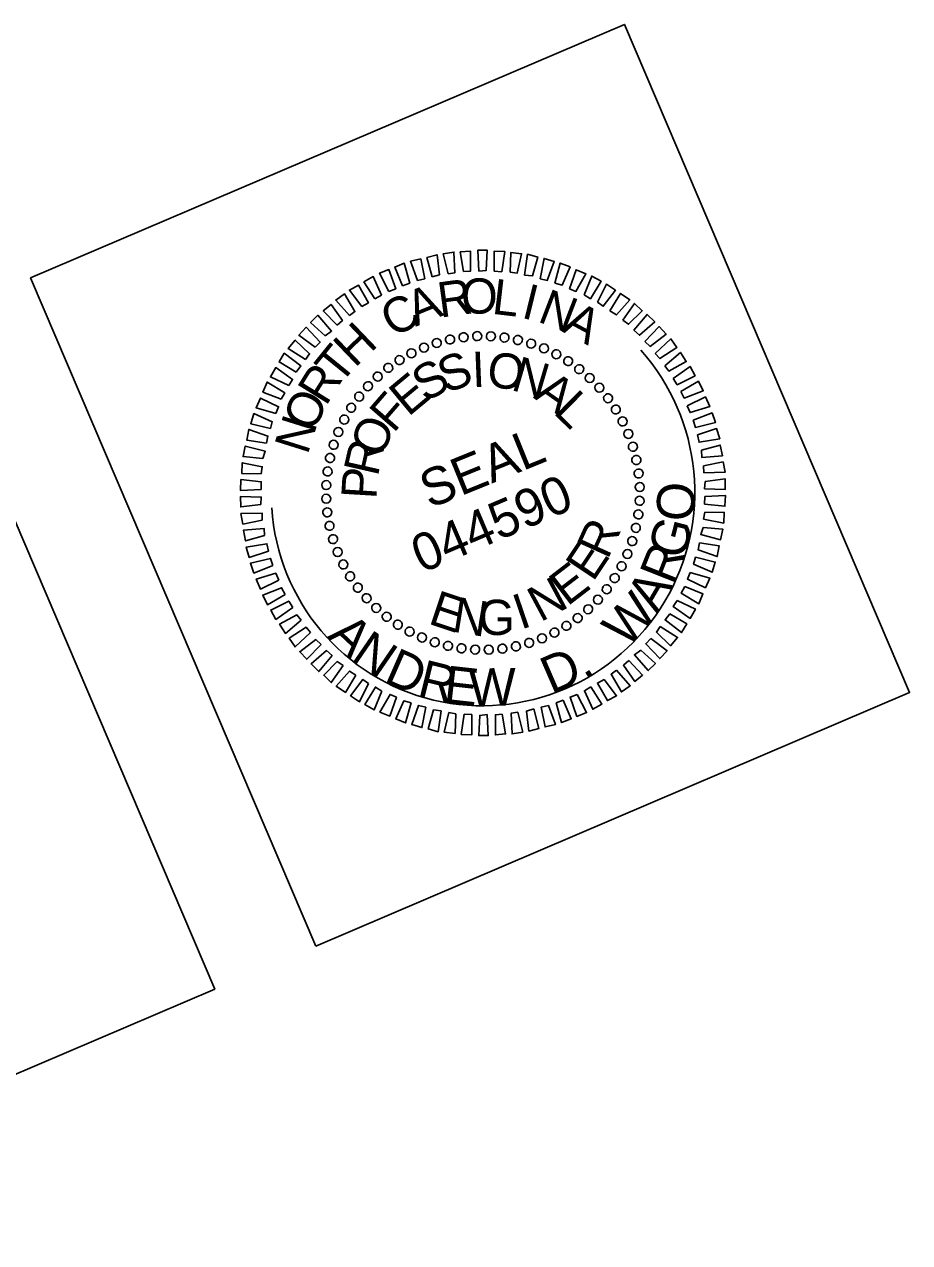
# Model space of a CAD drawing. Extents: x 1882804 to 2194450, y 87424 to 845437.
# Drawn here: x 2194312.8 to 2194449.9, y 87477.3 to 87666 of the extents above; entities that cross this region are included whole.
import ezdxf

# ---------------------------------------------------------------- set-up
doc = ezdxf.new("R2010")
doc.units = 0
for name, color, linetype in [('Scratch_Level_1', 7, 'Continuous'), ('Sheet PE Seal Cell', 7, 'Continuous'), ('Sheet Plot Border Inside CELL', 7, 'Continuous')]:
    doc.layers.add(name, color=color, linetype=linetype)

msp = doc.modelspace()

# ---------------------------------------------------------------- linework, layer by layer
at = {"layer": 'Scratch_Level_1'}
for points in [[(2194357.93, 87523.27), (2194449.9, 87562.54), (2194405.72, 87666.01), (2194313.75, 87626.74)], [(2194250.33, 87477.33), (2194342.29, 87516.6), (2194298.12, 87620.06), (2194206.15, 87580.8)]]:
    msp.add_lwpolyline(points, close=True, dxfattribs=at)
at = {"layer": 'Sheet PE Seal Cell'}
for p, q in [((2194374.67, 87615.97), (2194374.67, 87615.97)), ((2194376.69, 87616.67), (2194376.69, 87616.67)), ((2194378.74, 87617.18), (2194378.74, 87617.18)), ((2194380.78, 87617.58), (2194380.78, 87617.58)), ((2194382.92, 87617.75), (2194382.92, 87617.75)), ((2194385.04, 87617.71), (2194385.04, 87617.71)), ((2194387.16, 87617.56), (2194387.16, 87617.56)), ((2194389.24, 87617.13), (2194389.24, 87617.13)), ((2194391.31, 87616.6), (2194391.31, 87616.6)), ((2194372.73, 87615.09), (2194372.73, 87615.09)), ((2194393.26, 87615.85), (2194393.26, 87615.85)), ((2194395.22, 87614.95), (2194395.22, 87614.95)), ((2194369.12, 87612.81), (2194369.12, 87612.81)), ((2194370.93, 87614), (2194370.93, 87614)), ((2194397, 87613.87), (2194397, 87613.87)), ((2194398.75, 87612.61), (2194398.75, 87612.61)), ((2194367.48, 87611.48), (2194367.48, 87611.48)), ((2194400.38, 87611.25), (2194400.38, 87611.25)), ((2194364.64, 87608.37), (2194364.64, 87608.37)), ((2194366, 87610), (2194366, 87610)), ((2194401.86, 87609.78), (2194401.86, 87609.78)), ((2194363.39, 87606.62), (2194363.39, 87606.62)), ((2194403.19, 87608.13), (2194403.19, 87608.13)), ((2194362.3, 87604.84), (2194362.3, 87604.84)), ((2194404.38, 87606.33), (2194404.38, 87606.33)), ((2194361.4, 87602.88), (2194361.4, 87602.88)), ((2194405.47, 87604.53), (2194405.47, 87604.53)), ((2194360.66, 87600.93), (2194360.66, 87600.93)), ((2194406.35, 87602.58), (2194406.35, 87602.58)), ((2194407.05, 87600.57), (2194407.05, 87600.57)), ((2194360.12, 87598.86), (2194360.12, 87598.86)), ((2194407.56, 87598.52), (2194407.56, 87598.52)), ((2194359.69, 87596.78), (2194359.69, 87596.78)), ((2194407.96, 87596.48), (2194407.96, 87596.48)), ((2194359.54, 87594.66), (2194359.54, 87594.66)), ((2194408.13, 87594.34), (2194408.13, 87594.34)), ((2194359.5, 87592.54), (2194359.5, 87592.54)), ((2194408.09, 87592.21), (2194408.09, 87592.21)), ((2194359.68, 87590.4), (2194359.68, 87590.4)), ((2194407.94, 87590.1), (2194407.94, 87590.1)), ((2194360.07, 87588.36), (2194360.07, 87588.36)), ((2194407.51, 87588.02), (2194407.51, 87588.02)), ((2194360.58, 87586.31), (2194360.58, 87586.31)), ((2194406.98, 87585.95), (2194406.98, 87585.95)), ((2194361.28, 87584.29), (2194361.28, 87584.29)), ((2194406.23, 87583.99), (2194406.23, 87583.99)), ((2194362.16, 87582.35), (2194362.16, 87582.35)), ((2194405.33, 87582.03), (2194405.33, 87582.03)), ((2194363.25, 87580.55), (2194363.25, 87580.55)), ((2194404.25, 87580.25), (2194404.25, 87580.25)), ((2194364.44, 87578.74), (2194364.44, 87578.74)), ((2194402.99, 87578.5), (2194402.99, 87578.5)), ((2194365.78, 87577.1), (2194365.78, 87577.1)), ((2194401.63, 87576.87), (2194401.63, 87576.87)), ((2194367.25, 87575.62), (2194367.25, 87575.62)), ((2194400.16, 87575.4), (2194400.16, 87575.4)), ((2194368.88, 87574.26), (2194368.88, 87574.26)), ((2194370.63, 87573.01), (2194370.63, 87573.01)), ((2194396.71, 87572.87), (2194396.71, 87572.87)), ((2194398.51, 87574.06), (2194398.51, 87574.06)), ((2194372.41, 87571.92), (2194372.41, 87571.92)), ((2194374.37, 87571.02), (2194374.37, 87571.02)), ((2194392.96, 87570.9), (2194392.96, 87570.9)), ((2194394.91, 87571.78), (2194394.91, 87571.78)), ((2194376.32, 87570.28), (2194376.32, 87570.28)), ((2194378.4, 87569.74), (2194378.4, 87569.74)), ((2194380.48, 87569.31), (2194380.48, 87569.31)), ((2194382.59, 87569.16), (2194382.59, 87569.16)), ((2194384.72, 87569.12), (2194384.72, 87569.12)), ((2194386.86, 87569.3), (2194386.86, 87569.3)), ((2194388.9, 87569.69), (2194388.9, 87569.69)), ((2194390.95, 87570.2), (2194390.95, 87570.2))]:
    msp.add_line(p, q, dxfattribs=at)
for points in [[(2194383.17, 87627.76), (2194383, 87631.01), (2194384.47, 87631.01), (2194384.33, 87627.89)], [(2194373.67, 87626.34), (2194372.61, 87629.31), (2194374.19, 87629.67), (2194374.81, 87626.62)], [(2194375.96, 87626.9), (2194375.14, 87629.92), (2194376.71, 87630.32), (2194377.08, 87627.22)], [(2194378.44, 87627.38), (2194377.65, 87630.46), (2194379.31, 87630.75), (2194379.47, 87627.55)], [(2194380.82, 87627.71), (2194380.31, 87630.76), (2194381.88, 87630.9), (2194381.89, 87627.8)], [(2194385.54, 87627.77), (2194385.53, 87630.88), (2194387.18, 87630.84), (2194386.73, 87627.7)], [(2194388.02, 87627.62), (2194388.14, 87630.68), (2194389.8, 87630.49), (2194389.1, 87627.45)], [(2194390.27, 87627.16), (2194390.73, 87630.41), (2194392.29, 87629.97), (2194391.48, 87627.05)], [(2194392.67, 87626.61), (2194393.27, 87629.76), (2194394.85, 87629.27), (2194393.78, 87626.34)], [(2194369.22, 87624.65), (2194367.77, 87627.45), (2194369.25, 87628.04), (2194370.31, 87625.07)], [(2194371.38, 87625.52), (2194370.15, 87628.42), (2194371.63, 87629), (2194372.47, 87625.93)], [(2194394.95, 87625.95), (2194395.79, 87629.04), (2194397.32, 87628.43), (2194396.09, 87625.64)], [(2194397.22, 87625.07), (2194398.24, 87627.99), (2194399.77, 87627.37), (2194398.2, 87624.65)], [(2194365.07, 87622.3), (2194363.14, 87624.85), (2194364.55, 87625.61), (2194366.08, 87622.89)], [(2194367.09, 87623.48), (2194365.39, 87626.12), (2194366.82, 87626.95), (2194368.1, 87624.07)], [(2194399.47, 87624.14), (2194400.66, 87627.02), (2194402.11, 87626.21), (2194400.47, 87623.51)], [(2194401.54, 87622.97), (2194402.93, 87625.77), (2194404.33, 87624.84), (2194402.44, 87622.35)], [(2194363.14, 87620.9), (2194361.01, 87623.3), (2194362.39, 87624.26), (2194363.98, 87621.52)], [(2194403.48, 87621.64), (2194405.12, 87624.34), (2194406.54, 87623.36), (2194404.49, 87621.01)], [(2194361.25, 87619.4), (2194359.08, 87621.64), (2194360.29, 87622.63), (2194362.05, 87620.12)], [(2194405.48, 87620.17), (2194407.31, 87622.8), (2194408.48, 87621.66), (2194406.37, 87619.55)], [(2194359.37, 87617.76), (2194357.11, 87619.85), (2194358.22, 87620.95), (2194360.37, 87618.5)], [(2194407.19, 87618.64), (2194409.24, 87621.09), (2194410.43, 87619.92), (2194408.05, 87617.85)], [(2194357.81, 87615.99), (2194355.32, 87617.87), (2194356.43, 87619.09), (2194358.62, 87616.81)], [(2194408.88, 87616.88), (2194411.11, 87619.2), (2194412.19, 87618.03), (2194409.73, 87616.14)], [(2194356.35, 87614.1), (2194353.67, 87615.8), (2194354.75, 87617.1), (2194356.97, 87615)], [(2194410.51, 87615.05), (2194412.92, 87617.29), (2194413.82, 87615.94), (2194411.22, 87614.25)], [(2194354.87, 87612.15), (2194352.25, 87613.72), (2194353.04, 87615.06), (2194355.62, 87613.1)], [(2194411.96, 87613.14), (2194414.4, 87615.19), (2194415.31, 87613.79), (2194412.62, 87612.32)], [(2194353.74, 87610.09), (2194350.91, 87611.41), (2194351.72, 87612.86), (2194354.34, 87611.03)], [(2194413.27, 87611.17), (2194415.9, 87613.03), (2194416.68, 87611.58), (2194413.9, 87610.18)], [(2194352.55, 87607.95), (2194349.75, 87609.07), (2194350.37, 87610.6), (2194353.13, 87608.93)], [(2194414.45, 87609.15), (2194417.19, 87610.74), (2194417.93, 87609.27), (2194415, 87608.12)], [(2194351.75, 87605.76), (2194348.69, 87606.62), (2194349.37, 87608.12), (2194352.16, 87606.78)], [(2194415.45, 87606.94), (2194418.28, 87608.31), (2194418.93, 87606.8), (2194415.9, 87605.87)], [(2194350.91, 87603.4), (2194347.85, 87604.15), (2194348.34, 87605.73), (2194351.19, 87604.47)], [(2194416.35, 87604.69), (2194419.29, 87605.84), (2194419.82, 87604.33), (2194416.72, 87603.59)], [(2194350.3, 87601.14), (2194347.24, 87601.63), (2194347.54, 87603.28), (2194350.51, 87602.23)], [(2194417.04, 87602.46), (2194420.01, 87603.41), (2194420.48, 87601.82), (2194417.28, 87601.3)], [(2194417.66, 87600.04), (2194420.57, 87600.86), (2194420.9, 87599.21), (2194417.7, 87598.95)], [(2194349.72, 87598.79), (2194346.66, 87599.06), (2194347.01, 87600.69), (2194350.09, 87599.89)], [(2194349.47, 87596.42), (2194346.46, 87596.45), (2194346.53, 87598.11), (2194349.64, 87597.49)], [(2194417.99, 87597.65), (2194421, 87598.25), (2194421.31, 87596.65), (2194418.03, 87596.56)], [(2194349.45, 87593.99), (2194346.25, 87593.83), (2194346.33, 87595.5), (2194349.48, 87595.16)], [(2194418.23, 87595.23), (2194421.34, 87595.61), (2194421.35, 87593.98), (2194418.14, 87594.08)], [(2194349.4, 87591.65), (2194346.3, 87591.27), (2194346.28, 87592.9), (2194349.49, 87592.79)], [(2194418.18, 87592.89), (2194421.38, 87593.04), (2194421.3, 87591.38), (2194418.15, 87591.72)], [(2194349.64, 87589.22), (2194346.64, 87588.62), (2194346.32, 87590.23), (2194349.6, 87590.31)], [(2194418.16, 87590.46), (2194421.18, 87590.43), (2194421.1, 87588.76), (2194417.99, 87589.38)], [(2194349.98, 87586.84), (2194347.06, 87586.01), (2194346.73, 87587.66), (2194349.94, 87587.92)], [(2194417.91, 87588.09), (2194420.98, 87587.82), (2194420.62, 87586.19), (2194417.54, 87586.98)], [(2194417.34, 87585.73), (2194420.39, 87585.25), (2194420.09, 87583.59), (2194417.12, 87584.64)], [(2194350.59, 87584.41), (2194347.63, 87583.46), (2194347.16, 87585.05), (2194350.36, 87585.58)], [(2194351.28, 87582.18), (2194348.35, 87581.03), (2194347.81, 87582.54), (2194350.91, 87583.29)], [(2194416.72, 87583.47), (2194419.78, 87582.72), (2194419.3, 87581.15), (2194416.44, 87582.4)], [(2194352.19, 87579.93), (2194349.35, 87578.56), (2194348.7, 87580.08), (2194351.73, 87581)], [(2194415.89, 87581.11), (2194418.94, 87580.26), (2194418.26, 87578.76), (2194415.48, 87580.09)], [(2194353.18, 87577.72), (2194350.44, 87576.13), (2194349.7, 87577.61), (2194352.64, 87578.76)], [(2194415.08, 87578.93), (2194417.88, 87577.8), (2194417.27, 87576.28), (2194414.5, 87577.94)], [(2194354.36, 87575.7), (2194351.74, 87573.84), (2194350.95, 87575.3), (2194353.73, 87576.69)], [(2194413.89, 87576.78), (2194416.72, 87575.46), (2194415.92, 87574.01), (2194413.29, 87575.84)], [(2194355.68, 87573.73), (2194353.23, 87571.69), (2194352.32, 87573.09), (2194355.01, 87574.55)], [(2194412.77, 87574.72), (2194415.39, 87573.16), (2194414.59, 87571.82), (2194412.02, 87573.77)], [(2194357.13, 87571.82), (2194354.71, 87569.58), (2194353.82, 87570.94), (2194356.41, 87572.63)], [(2194411.28, 87572.77), (2194413.96, 87571.07), (2194412.88, 87569.77), (2194410.67, 87571.88)], [(2194358.75, 87569.99), (2194356.53, 87567.67), (2194355.45, 87568.84), (2194357.91, 87570.73)], [(2194409.82, 87570.89), (2194412.32, 87569), (2194411.2, 87567.79), (2194409.02, 87570.07)], [(2194360.45, 87568.24), (2194358.39, 87565.78), (2194357.2, 87566.96), (2194359.58, 87569.03)], [(2194408.26, 87569.11), (2194410.53, 87567.03), (2194409.42, 87565.92), (2194407.26, 87568.37)], [(2194362.16, 87566.7), (2194360.33, 87564.08), (2194359.16, 87565.21), (2194361.26, 87567.32)], [(2194406.39, 87567.47), (2194408.55, 87565.23), (2194407.34, 87564.24), (2194405.58, 87566.76)], [(2194364.15, 87565.24), (2194362.51, 87562.54), (2194361.1, 87563.51), (2194363.15, 87565.86)], [(2194404.49, 87565.98), (2194406.63, 87563.57), (2194405.25, 87562.61), (2194403.65, 87565.36)], [(2194366.09, 87563.91), (2194364.71, 87561.1), (2194363.31, 87562.03), (2194365.19, 87564.52)], [(2194368.17, 87562.74), (2194366.97, 87559.86), (2194365.53, 87560.66), (2194367.16, 87563.36)], [(2194400.54, 87563.39), (2194402.25, 87560.75), (2194400.81, 87559.93), (2194399.53, 87562.8)], [(2194402.57, 87564.57), (2194404.5, 87562.03), (2194403.08, 87561.27), (2194401.55, 87563.98)], [(2194370.41, 87561.8), (2194369.39, 87558.89), (2194367.86, 87559.5), (2194369.44, 87562.23)], [(2194372.68, 87560.93), (2194371.84, 87557.83), (2194370.32, 87558.44), (2194371.55, 87561.23)], [(2194396.25, 87561.35), (2194397.49, 87558.46), (2194396, 87557.87), (2194395.16, 87560.94)], [(2194398.41, 87562.22), (2194399.87, 87559.42), (2194398.38, 87558.84), (2194397.32, 87561.81)], [(2194374.96, 87560.27), (2194374.36, 87557.11), (2194372.78, 87557.6), (2194373.85, 87560.53)], [(2194377.36, 87559.71), (2194376.9, 87556.46), (2194375.35, 87556.9), (2194376.15, 87559.83)], [(2194379.61, 87559.25), (2194379.49, 87556.2), (2194377.83, 87556.38), (2194378.54, 87559.42)], [(2194389.2, 87559.5), (2194389.99, 87556.41), (2194388.32, 87556.12), (2194388.17, 87559.32)], [(2194391.68, 87559.98), (2194392.49, 87556.96), (2194390.93, 87556.55), (2194390.55, 87559.66)], [(2194393.97, 87560.53), (2194395.03, 87557.56), (2194393.44, 87557.2), (2194392.82, 87560.26)], [(2194382.1, 87559.1), (2194382.11, 87556), (2194380.46, 87556.03), (2194380.91, 87559.17)], [(2194384.46, 87559.11), (2194384.64, 87555.87), (2194383.16, 87555.87), (2194383.31, 87558.98)], [(2194386.81, 87559.16), (2194387.32, 87556.12), (2194385.75, 87555.97), (2194385.74, 87559.08)]]:
    msp.add_lwpolyline(points, close=True, dxfattribs=at)
for centre, major_axis in [((2194378.72, 87617.19), (-0.146, 0.682)), ((2194380.81, 87617.55), (-0.086, 0.692)), ((2194382.92, 87617.72), (-0.026, 0.697)), ((2194385.04, 87617.7), (0.035, 0.697)), ((2194387.15, 87617.5), (0.096, 0.691)), ((2194389.23, 87617.12), (0.155, 0.68)), ((2194374.67, 87615.95), (-0.263, 0.646)), ((2194376.66, 87616.66), (-0.205, 0.667)), ((2194391.28, 87616.56), (0.214, 0.664)), ((2194393.26, 87615.82), (0.271, 0.643)), ((2194370.9, 87614.01), (-0.371, 0.591)), ((2194372.74, 87615.06), (-0.318, 0.621)), ((2194395.18, 87614.91), (0.326, 0.617)), ((2194397.01, 87613.84), (0.379, 0.586)), ((2194367.52, 87611.46), (-0.468, 0.517)), ((2194369.15, 87612.81), (-0.421, 0.556)), ((2194398.73, 87612.61), (0.428, 0.551)), ((2194366.01, 87609.97), (-0.511, 0.475)), ((2194400.35, 87611.24), (0.475, 0.511)), ((2194401.84, 87609.73), (0.517, 0.468)), ((2194364.64, 87608.36), (-0.551, 0.428)), ((2194403.19, 87608.1), (0.556, 0.421)), ((2194363.41, 87606.63), (-0.586, 0.379)), ((2194404.39, 87606.36), (0.591, 0.371)), ((2194362.34, 87604.8), (-0.617, 0.326)), ((2194405.44, 87604.51), (0.621, 0.318)), ((2194361.43, 87602.88), (-0.643, 0.271)), ((2194406.32, 87602.59), (0.646, 0.263)), ((2194360.69, 87600.9), (-0.664, 0.214)), ((2194407.04, 87600.59), (0.667, 0.205)), ((2194360.13, 87598.85), (-0.68, 0.155)), ((2194407.57, 87598.54), (0.682, 0.146)), ((2194359.75, 87596.77), (-0.691, 0.096)), ((2194407.93, 87596.45), (0.692, 0.086)), ((2194359.55, 87594.66), (-0.697, 0.035)), ((2194408.1, 87594.34), (0.697, 0.026)), ((2194359.54, 87592.54), (-0.697, -0.026)), ((2194408.08, 87592.22), (0.697, -0.035)), ((2194359.71, 87590.43), (-0.692, -0.086)), ((2194407.88, 87590.11), (0.691, -0.096)), ((2194360.06, 87588.34), (-0.682, -0.146)), ((2194407.5, 87588.02), (0.68, -0.155)), ((2194360.6, 87586.28), (-0.667, -0.205)), ((2194406.94, 87585.98), (0.664, -0.214)), ((2194361.31, 87584.29), (-0.646, -0.263)), ((2194406.2, 87583.99), (0.643, -0.271)), ((2194362.19, 87582.36), (-0.621, -0.318)), ((2194405.29, 87582.08), (0.617, -0.326)), ((2194363.24, 87580.52), (-0.591, -0.371)), ((2194404.22, 87580.25), (0.586, -0.379)), ((2194364.44, 87578.77), (-0.556, -0.421)), ((2194402.99, 87578.52), (0.551, -0.428)), ((2194365.8, 87577.14), (-0.517, -0.468)), ((2194367.28, 87575.63), (-0.475, -0.511)), ((2194401.62, 87576.9), (0.511, -0.475)), ((2194368.9, 87574.26), (-0.428, -0.551)), ((2194398.48, 87574.06), (0.421, -0.556)), ((2194400.11, 87575.42), (0.468, -0.517)), ((2194370.63, 87573.03), (-0.379, -0.586)), ((2194372.46, 87571.96), (-0.326, -0.617)), ((2194394.89, 87571.81), (0.318, -0.621)), ((2194396.74, 87572.86), (0.371, -0.591)), ((2194374.37, 87571.05), (-0.271, -0.643)), ((2194376.36, 87570.31), (-0.214, -0.664)), ((2194390.97, 87570.22), (0.205, -0.667)), ((2194392.97, 87570.93), (0.263, -0.646)), ((2194378.4, 87569.75), (-0.155, -0.68)), ((2194380.49, 87569.37), (-0.096, -0.691)), ((2194382.6, 87569.17), (-0.035, -0.697)), ((2194384.72, 87569.16), (0.026, -0.697)), ((2194386.83, 87569.33), (0.086, -0.692)), ((2194388.92, 87569.68), (0.146, -0.682))]:
    msp.add_ellipse(centre, major_axis=major_axis, ratio=0.999708, dxfattribs=at)
at = {"layer": 'Sheet Plot Border Inside CELL'}
msp.add_ellipse((2194383.82, 87593.44), major_axis=(10.38, 31.31), ratio=0.993455, start_param=1.958957, end_param=5.764947, dxfattribs=at)

# ---------------------------------------------------------------- texts
at = {"layer": 'Sheet PE Seal Cell'}
for s, height, rotation, p in [('R', 5.46, 7.7417, (2194377.18, 87620.57)), ('O', 5.46, 0.5417, (2194380.45, 87621.18)), ('L', 5.46, 353.3414, (2194385.08, 87621.2)), ('I', 5.46, 346.1407, (2194389.6, 87620.61)), ('C', 5.46, 29.3404, (2194369.96, 87617.38)), ('A', 5.46, 22.1409, (2194373.36, 87619.15)), ('N', 5.46, 338.9395, (2194392.1, 87620.04)), ('A', 5.46, 331.7377, (2194395.85, 87618.54)), ('H', 5.46, 43.74, (2194363.95, 87612.71)), ('T', 5.46, 50.9403, (2194361.68, 87610)), ('S', 5.46, 21.021, (2194378.1, 87608.8)), ('I', 5.46, 2.3102, (2194382.2, 87609.81)), ('O', 5.46, 352.9541, (2194384.25, 87609.95)), ('N', 5.46, 343.5972, (2194387.99, 87609.44)), ('R', 5.46, 58.1411, (2194359.49, 87606.75)), ('E', 5.46, 39.7316, (2194372.24, 87605.14)), ('S', 5.46, 30.3762, (2194374.91, 87607.38)), ('A', 5.46, 324.8808, (2194391.52, 87608.21)), ('O', 5.46, 65.3423, (2194357.59, 87602.68)), ('F', 5.46, 49.0876, (2194369.96, 87602.58)), ('L', 5.46, 315.5214, (2194394.57, 87605.88)), ('N', 5.46, 72.5441, (2194356.65, 87599.22)), ('O', 5.46, 67.8018, (2194368.14, 87598.7)), ('SEAL', 5.811, 22.1206, (2194375.55, 87590.96)), ('R', 5.46, 77.1602, (2194367.51, 87595.85)), ('P', 5.46, 86.5195, (2194367.3, 87592.39)), ('044590 ', 5.811, 23.1206, (2194374.35, 87580.96)), ('O', 5.81, 86.2878, (2194416.38, 87588.91)), ('R', 5.46, 65.602, (2194403.13, 87582.99)), ('G', 5.81, 75.7356, (2194414.97, 87582.95)), ('E', 5.46, 56.2447, (2194400.86, 87579.54)), ('R', 5.81, 68.3806, (2194413.35, 87579)), ('E', 5.46, 37.5323, (2194396.88, 87575.79)), ('N', 5.46, 28.177, (2194392.7, 87573.37)), ('A', 5.81, 59.6851, (2194410.8, 87574.64)), ('E', 5.46, 341.3975, (2194375.16, 87573.26)), ('W', 5.81, 47.3366, (2194406.12, 87569.23)), ('N', 5.46, 350.7545, (2194378.86, 87571.99)), ('G', 5.46, 0.1108, (2194383.1, 87571.43)), ('I', 5.46, 18.8218, (2194389.66, 87572.23)), ('A', 5.81, 316.6721, (2194359.5, 87571.08)), ('N', 5.81, 325.5155, (2194363.17, 87567.62)), ('D', 5.81, 336.2635, (2194368.27, 87564.24)), ('D', 5.81, 23.4641, (2194394.41, 87562.18)), ('R', 5.81, 346.1664, (2194373.45, 87562.02)), ('E', 5.81, 353.6644, (2194377.59, 87560.95)), ('W', 5.81, 0.7835, (2194381.62, 87560.44)), ('.', 5.81, 33.2652, (2194399.56, 87564.47))]:
    msp.add_text(s, height=height, rotation=rotation, dxfattribs=at).set_placement(p)

doc.saveas('drawing.dxf')
